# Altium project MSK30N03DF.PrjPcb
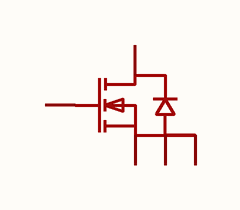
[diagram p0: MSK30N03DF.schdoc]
1 sheet, 1 parts. Net scope: global (net labels, ports and power ports of the same name join across sheets).

## Sheet MSK30N03DF.schdoc
size 127 x 101 mm

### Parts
Q?  msk30n03df  [DFN-8_L3.3-W3.3-P0.65-BL-2]  (value not drawn)

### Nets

Not connected (* = marked no-connect by the designer): Q? 1(S) 2(S) 3(S) 4(G) 5(D)

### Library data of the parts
Q? = msk30n03df: 数量:1个N沟道;漏源电压(Vdss):30V;连续漏极电流(Id):30A;导通电阻(RDS(on)):9mΩ@10V;耗散功率(Pd):20W;阈值电压(Vgs(th)):2.5V;; Manufacturer: MSKSEMI(美森科); AddInBom: yes; ModelId: 720567037d40416ca2f14c632ba061bb; ModelTransform: 129.921,130.708,0,0,0,0,0.196,33.275,0; Number: 1个N沟道; Drain to Source Voltage: 30V; Current - Continuous Drain(Id): 30A; Pd - Power Dissipation: 20W; Gate Threshold Voltage (Vgs(th)): 2.5V; Gate Charge(Qg): 7.2nC@4.5V; Input Capacitance(Ciss): 572pF; Reverse Transfer Capacitance (Crss@Vds): 65pF; Type: N沟道; Output Capacitance(Coss): 81pF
